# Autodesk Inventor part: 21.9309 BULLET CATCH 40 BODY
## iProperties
Created: 2012-06
Part Number: 21.9309 BULLET CATCH 40 BODY
Document SubType Name: Modeling
Designer: Administrator
Density: 1.06 g/cm^3
Material: ABS Plastic
Mass: 12.3233 g
Surface Area: 102.481 cm^2
Volume: 11.6257 cm^3
Author: Administrator
